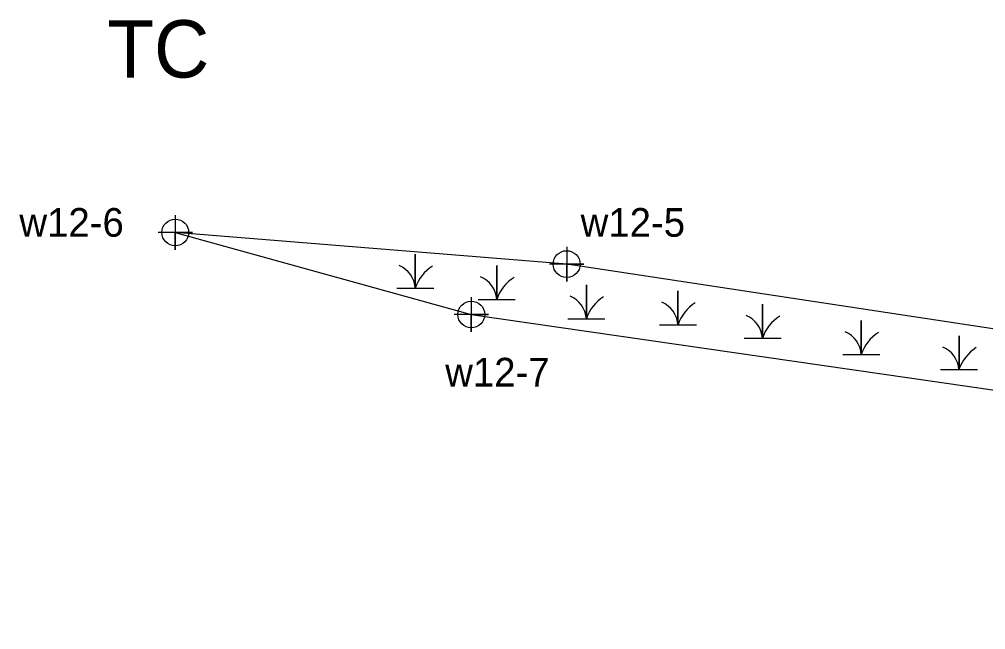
# Model space of a CAD drawing. Extents: x 2174810 to 2196950, y 76168 to 88270.
# Drawn here: x 2191949.5 to 2192118.1, y 86910.8 to 87017.2 of the extents above; entities that cross this region are included whole.
import ezdxf

# ---------------------------------------------------------------- set-up
doc = ezdxf.new("R2010")
doc.units = 0
for name, color, linetype in [('Exist Environmental Wetland Boundary', 7, 'Continuous'), ('Exist Environmental Wetland Boundary Cogo Point CELL', 7, 'Continuous'), ('Exist Hydro Jurisdictional Stream or Body of Water Mitigable Cogo Number', 7, 'Continuous'), ('Exist Hydro Jurisdictional Stream or Body of Water NonMitigable Text', 7, 'Continuous'), ('Exist Hydro Swamp or Marsh', 7, 'Continuous')]:
    doc.layers.add(name, color=color, linetype=linetype)

msp = doc.modelspace()

# ---------------------------------------------------------------- linework, layer by layer
at = {"layer": 'Exist Environmental Wetland Boundary'}
msp.add_lwpolyline([(2192359.72, 86910.76), (2192412.81, 86942.8), (2192320.42, 86951.32), (2192243.31, 86951.23), (2192143.88, 86959.49), (2192045.01, 86974.5), (2191976.74, 86980.02), (2192028.37, 86965.72), (2192140.6, 86949.53), (2192233.5, 86933.52), (2192319.76, 86918.46)], close=True, dxfattribs=at)
at = {"layer": 'Exist Environmental Wetland Boundary Cogo Point CELL'}
for points in [[(2191976.74, 86983.02), (2191976.74, 86977.02), (2191976.74, 86980.02), (2191979.74, 86980.02), (2191973.74, 86980.02)], [(2192045.01, 86977.5), (2192045.01, 86971.5), (2192045.01, 86974.5), (2192048.01, 86974.5), (2192042.01, 86974.5)], [(2192028.37, 86968.72), (2192028.37, 86962.72), (2192028.37, 86965.72), (2192031.37, 86965.72), (2192025.37, 86965.72)]]:
    msp.add_lwpolyline(points, dxfattribs=at)
for centre in [(2191976.74, 86980.02), (2192045.01, 86974.5), (2192028.37, 86965.72)]:
    msp.add_circle(centre, 2.34, dxfattribs=at)
at = {"layer": 'Exist Hydro Swamp or Marsh'}
for points in [[(2192015.39, 86970.31), (2192018.61, 86970.31), (2192018.61, 86976.23), (2192018.61, 86970.31), (2192021.84, 86970.31)], [(2192029.59, 86968.36), (2192032.82, 86968.36), (2192032.82, 86974.28), (2192032.82, 86968.36), (2192036.04, 86968.36)], [(2192045.22, 86964.98), (2192048.44, 86964.98), (2192048.44, 86970.9), (2192048.44, 86964.98), (2192051.67, 86964.98)], [(2192061.2, 86963.92), (2192064.42, 86963.92), (2192064.42, 86969.84), (2192064.42, 86963.92), (2192067.65, 86963.92)], [(2192075.94, 86961.61), (2192079.16, 86961.61), (2192079.16, 86967.53), (2192079.16, 86961.61), (2192082.39, 86961.61)], [(2192093.16, 86958.77), (2192096.39, 86958.77), (2192096.39, 86964.69), (2192096.39, 86958.77), (2192099.61, 86958.77)], [(2192110.21, 86956.1), (2192113.43, 86956.1), (2192113.43, 86962.02), (2192113.43, 86956.1), (2192116.66, 86956.1)]]:
    msp.add_lwpolyline(points, dxfattribs=at)
for centre, radius, start, end in [((2192014.01, 86969.98), 4.61, 4.1403, 67.535), ((2192025.45, 86968.04), 7.21, 122.1274, 161.6222), ((2192028.22, 86968.03), 4.61, 4.1403, 67.535), ((2192039.66, 86966.09), 7.21, 122.1274, 161.6222), ((2192043.84, 86964.65), 4.61, 4.1403, 67.535), ((2192055.28, 86962.71), 7.21, 122.1274, 161.6222), ((2192059.82, 86963.59), 4.61, 4.1403, 67.535), ((2192071.27, 86961.65), 7.21, 122.1274, 161.6222), ((2192074.56, 86961.28), 4.61, 4.1403, 67.535), ((2192086, 86959.34), 7.21, 122.1274, 161.6222), ((2192091.79, 86958.43), 4.61, 4.1403, 67.535), ((2192103.23, 86956.49), 7.21, 122.1274, 161.6222), ((2192108.83, 86955.77), 4.61, 4.1403, 67.535), ((2192120.27, 86953.83), 7.21, 122.1274, 161.6222)]:
    msp.add_arc(centre, radius, start, end, dxfattribs=at)

# ---------------------------------------------------------------- texts
at = {"layer": 'Exist Hydro Jurisdictional Stream or Body of Water Mitigable Cogo Number'}
for s, p in [('w12-6', (2191949.56, 86979.28)), ('w12-5', (2192047.44, 86979.28)), ('w12-7', (2192023.82, 86953.16))]:
    msp.add_text(s, height=5, dxfattribs=at).set_placement(p)
at = {"layer": 'Exist Hydro Jurisdictional Stream or Body of Water NonMitigable Text'}
msp.add_text('TC', height=10, dxfattribs=at).set_placement((2191964.86, 87007.04))

doc.saveas('drawing.dxf')
